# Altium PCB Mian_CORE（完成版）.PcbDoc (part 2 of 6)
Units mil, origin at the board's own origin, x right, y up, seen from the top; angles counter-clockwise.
Board outline 2755.91 x 1771.65 mil, 4 copper layers (TOP, GND02, PWR03, BOTTOM); 61 components, 130 nets, 4907 pads, 497 vias.
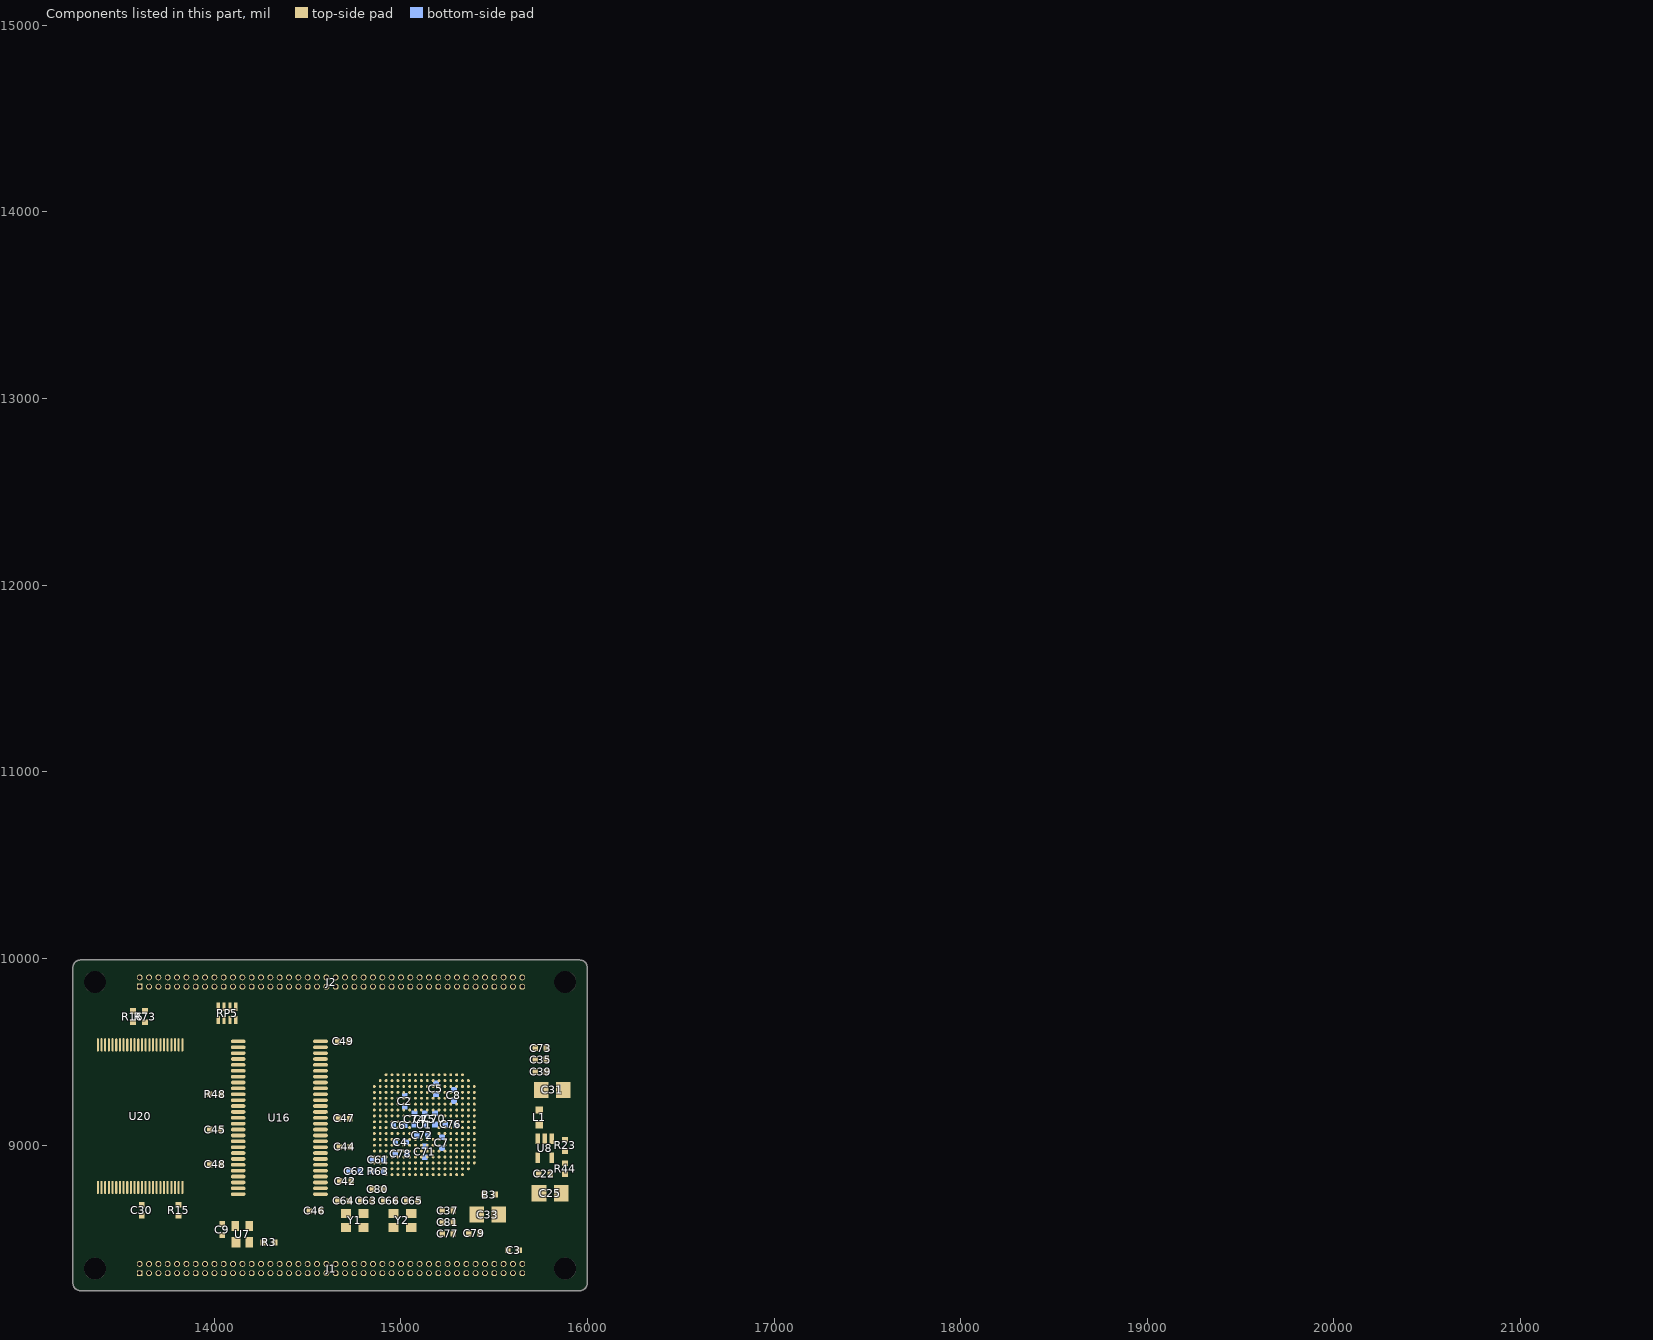
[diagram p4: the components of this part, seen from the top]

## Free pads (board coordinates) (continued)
  round 6 on Drill Drawing: 1(17801.05,10105.03) 1(17801.05,10325.03) 1(17801.05,10545.03) 1(17804.4,9445.61) 1(17804.4,9445.61) 1(17804.4,9480.61) 1(17824.4,9445.61) 1(17831.9,9445.61) 1(17836.4,9457.86) 1(17844.4,9480.61) 1(17844.4,9480.61) 1(17852.4,9457.86) 1(17856.9,9445.61) 1(17864.4,9480.61) 1(17874.4,9445.61) 1(17874.4,9461.36) 1(17874.4,9461.36) 1(17874.4,9461.36) 1(17881.05,10085.03) 1(17881.05,10085.03) 1(17881.05,10125.03) 1(17881.05,10125.03) 1(17881.05,10305.03) 1(17881.05,10305.03) 1(17881.05,10345.03) 1(17881.05,10345.03) 1(17881.05,10525.03) 1(17881.05,10525.03) 1(17881.05,10565.03) 1(17881.05,10565.03) 1(17884.4,9480.61) 1(17889.05,8796.36) 1(17889.05,8796.36) 1(17889.05,8831.36) 1(17894.4,9445.61) 1(17894.4,9445.61) 1(17894.4,9463.69) 1(17894.4,9480.61) 1(17894.4,9480.61) 1(17906.4,9463.69) 1(17909.05,8796.36) 1(17914.4,9445.61) 1(17914.4,9480.61) 1(17916.55,8796.36) 1(17921.05,8808.61) 1(17924.4,9445.61) 1(17924.4,9462.53) 1(17924.4,9480.61) 1(17924.4,9480.61) 1(17929.05,8831.36) 1(17929.05,8831.36) 1(17936.05,10105.03) 1(17936.05,10105.03) 1(17936.05,10105.03) 1(17936.05,10325.03) 1(17936.05,10325.03) 1(17936.05,10325.03) 1(17936.05,10545.03) 1(17936.05,10545.03) 1(17936.05,10545.03) 1(17936.9,9462.53) 1(17936.9,9462.53) 1(17936.9,9462.53) 1(17936.9,9480.61) 1(17936.9,9480.61) 1(17937.05,8808.61) 1(17940.4,9464.28) 1(17940.4,9464.28) 1(17940.9,9478.86) 1(17940.9,9478.86) 1(17941.55,8796.36) 1(17943.4,9467.19) 1(17943.4,9467.19) 1(17943.4,9476.53) 1(17943.4,9476.53) 1(17944.4,9445.61) 1(17944.4,9471.86) 1(17944.4,9471.86) 1(17949.05,8831.36) 1(17959.05,8796.36) 1(17959.05,8812.11) 1(17959.05,8812.11) 1(17959.05,8812.11) 1(17969.05,8831.36) 1(17979.05,8796.36) 1(17979.05,8796.36) 1(17979.05,8814.44) 1(17979.05,8831.36) 1(17979.05,8831.36) 1(17991.05,8814.44) 1(17999.05,8796.36) 1(17999.05,8831.36) 1(18009.05,8796.36) 1(18009.05,8813.28) 1(18009.05,8831.36) 1(18009.05,8831.36) 1(18021.55,8813.28) 1(18021.55,8813.28) 1(18021.55,8813.28) 1(18021.55,8831.36) 1(18021.55,8831.36) 1(18025.05,8815.03) 1(18025.05,8815.03) 1(18025.55,8829.61) 1(18025.55,8829.61) 1(18028.05,8817.94) 1(18028.05,8817.94) 1(18028.05,8827.28) 1(18028.05,8827.28) 1(18029.05,8796.36) 1(18029.05,8822.61) 1(18029.05,8822.61) 1(18031.55,10069.6) 1(18031.55,10119.6) 1(18031.55,10289.29) 1(18031.55,10339.29) 1(18031.55,10508.97) 1(18031.55,10558.97) 1(18066.55,10054.6) 1(18066.55,10274.29) 1(18066.55,10493.97) 1(18071.55,10159.6) 1(18071.55,10379.29) 1(18071.55,10598.97) 1(18116.55,10054.6) 1(18116.55,10274.29) 1(18116.55,10493.97) 1(18121.55,10159.6) 1(18121.55,10379.29) 1(18121.55,10598.97) 1(18166.55,10054.6) 1(18166.55,10274.29) 1(18166.55,10493.97) 1(18171.55,10159.6) 1(18171.55,10379.29) 1(18171.55,10598.97) 1(18221.55,10159.6) 1(18221.55,10379.29) 1(18221.55,10598.97) 1(18271.55,10159.6) 1(18271.55,10379.29) 1(18271.55,10598.97) 1(18278.95,9479.58) 1(18285.95,9444.58) 1(18285.95,9444.58) 1(18293.95,9479.58) 1(18293.95,9479.58) 1(18301.95,9444.58) 1(18301.95,9444.58) 1(18308.95,9479.58) 1(18313.58,8840.03) 1(18317.95,9444.58) 1(18317.95,9479.58) 1(18320.58,8805.03) 1(18320.58,8805.03) 1(18323.95,9444.58) 1(18323.95,9479.58) 1(18328.58,8840.03) 1(18328.58,8840.03) 1(18329.95,9444.58) 1(18329.95,9479.58) 1(18336.58,8805.03) 1(18336.58,8805.03) 1(18342.95,9444.58) 1(18342.95,9444.58) 1(18342.95,9479.58) 1(18342.95,9479.58) 1(18343.58,8840.03) 1(18352.58,8805.03) 1(18352.58,8840.03) 1(18352.95,9444.58) 1(18352.95,9444.58) 1(18352.95,9479.58) 1(18352.95,9479.58) 1(18356.95,9446.33) 1(18356.95,9446.33) 1(18356.95,9477.83) 1(18356.95,9477.83) 1(18358.58,8805.03) 1(18358.58,8840.03) 1(18359.95,9448.66) 1(18359.95,9448.66) 1(18359.95,9475.5) 1(18359.95,9475.5) 1(18362.45,9452.16) 1(18362.45,9452.16) 1(18362.45,9472) 1(18362.45,9472) 1(18364.45,9456.25) 1(18364.45,9456.25) 1(18364.45,9467.91) 1(18364.45,9467.91) 1(18364.58,8805.03) 1(18364.58,8840.03) 1(18364.95,9462.08) 1(18364.95,9462.08) 1(18372.45,9479.58) 1(18377.58,8805.03) 1(18377.58,8805.03) 1(18377.58,8840.03) 1(18377.58,8840.03) 1(18383.95,9444.58) 1(18383.95,9479.58) 1(18387.58,8805.03) 1(18387.58,8805.03) 1(18387.58,8840.03) 1(18387.58,8840.03) 1(18391.58,8806.78) 1(18391.58,8806.78) 1(18391.58,8838.28) 1(18391.58,8838.28) 1(18394.58,8809.11) 1(18394.58,8809.11) 1(18394.58,8835.95) 1(18394.58,8835.95) 1(18395.45,9479.58) 1(18397.08,8812.61) 1(18397.08,8812.61) 1(18397.08,8832.45) 1(18397.08,8832.45) 1(18399.08,8816.7) 1(18399.08,8816.7) 1(18399.08,8828.36) 1(18399.08,8828.36) 1(18399.58,8822.53) 1(18399.58,8822.53) 1(18403.45,9444.58) 1(18403.45,9462.08) 1(18403.45,9479.58) 1(18407.08,8840.03) 1(18418.58,8805.03) 1(18418.58,8840.03) 1(18424.45,9444.58) 1(18424.45,9462.08) 1(18424.45,9479.58) 1(18430.08,8840.03) 1(18438.08,8805.03) 1(18438.08,8822.53) 1(18438.08,8840.03) 1(18459.08,8805.03) 1(18459.08,8822.53) 1(18459.08,8840.03) 1(18511.26,9452.75) 1(18511.26,9452.75) 1(18511.26,9476.08) 1(18511.26,9476.08) 1(18513.76,9446.92) 1(18513.76,9446.92) 1(18513.76,9481.92) 1(18513.76,9481.92) 1(18518.58,8805.03) 1(18518.58,8805.03) 1(18518.58,8828.36) 1(18518.58,8828.36) 1(18518.76,9441.08) 1(18518.76,9487.75) 1(18521.08,8799.2) 1(18521.08,8799.2) 1(18521.08,8834.2) 1(18521.08,8834.2) 1(18526.08,8793.36) 1(18526.08,8840.03) 1(18536.26,9452.75) 1(18536.26,9469.67) 1(18536.26,9476.08) 1(18537.76,9472.58) 1(18537.76,9472.58) 1(18540.26,9474.92) 1(18540.26,9474.92) 1(18543.58,8805.03) 1(18543.58,8821.95) 1(18543.58,8828.36) 1(18543.76,9476.08) 1(18543.76,9476.08) 1(18545.08,8824.86) 1(18545.08,8824.86) 1(18547.26,9474.92) 1(18547.26,9474.92) 1(18547.58,8827.2) 1(18547.58,8827.2) 1(18549.76,9472.58) 1(18549.76,9472.58) 1(18551.08,8828.36) 1(18551.08,8828.36) 1(18551.26,9452.75) 1(18551.26,9469.67) 1(18551.26,9469.67) 1(18551.26,9469.67) 1(18552.76,9472.58) 1(18552.76,9472.58) 1(18554.58,8827.2) 1(18554.58,8827.2) 1(18555.26,9474.92) 1(18555.26,9474.92) 1(18557.08,8824.86) 1(18557.08,8824.86) 1(18558.58,8805.03) 1(18558.58,8821.95) 1(18558.58,8821.95) 1(18558.58,8821.95) 1(18558.76,9476.08) 1(18558.76,9476.08) 1(18560.08,8824.86) 1(18560.08,8824.86) 1(18562.26,9474.92) 1(18562.26,9474.92) 1(18562.58,8827.2) 1(18562.58,8827.2) 1(18564.76,9472.58) 1(18564.76,9472.58) 1(18566.08,8828.36) 1(18566.08,8828.36) 1(18566.26,9452.75) 1(18566.26,9469.08) 1(18566.26,9469.08) 1(18569.58,8827.2) 1(18569.58,8827.2) 1(18572.08,8824.86) 1(18572.08,8824.86) 1(18573.58,8805.03) 1(18573.58,8821.36) 1(18573.58,8821.36) 1(18580.26,9486) 1(18580.26,9486) 1(18580.26,9487.17) 1(18580.26,9487.17) 1(18581.26,9452.75) 1(18581.26,9476.08) 1(18581.26,9485.42) 1(18581.26,9485.42) 1(18581.26,9487.75) 1(18581.26,9487.75) 1(18582.26,9486) 1(18582.26,9486) 1(18582.26,9487.17) 1(18582.26,9487.17) 1(18587.58,8838.28) 1(18587.58,8838.28) 1(18587.58,8839.45) 1(18587.58,8839.45) 1(18588.58,8805.03) 1(18588.58,8828.36) 1(18588.58,8837.7) 1(18588.58,8837.7) 1(18588.58,8840.03) 1(18588.58,8840.03) 1(18589.58,8838.28) 1(18589.58,8838.28) 1(18589.58,8839.45) 1(18589.58,8839.45) 1(18611.26,9452.75) 1(18611.26,9487.75) 1(18614.09,11174.91) 1(18614.09,11174.91) 1(18614.09,11237.91) 1(18618.26,11157.91) 1(18618.58,8805.03) 1(18618.58,8840.03) 1(18643.76,9441.08) 1(18643.76,9487.75) 1(18645.43,11174.91) 1(18648.76,9446.92) 1(18648.76,9446.92) 1(18648.76,9481.92) 1(18648.76,9481.92) 1(18651.08,8793.36) 1(18651.08,8840.03) 1(18651.26,9452.75) 1(18651.26,9452.75) 1(18651.26,9476.08) 1(18651.26,9476.08) 1(18656.08,8799.2) 1(18656.08,8799.2) 1(18656.08,8834.2) 1(18656.08,8834.2) 1(18658.58,8805.03) 1(18658.58,8805.03) 1(18658.58,8828.36) 1(18658.58,8828.36) 1(18673.18,11174.91) 1(18680.23,11196.96) 1(18692.76,11237.91) 1(18692.76,11237.91) 1(18705.29,11196.96) 1(18712.34,11174.91) 1(18727.35,9837.19) 1(18727.35,9837.19) 1(18727.35,9870.79) 1(18727.35,9900.19) 1(18727.35,9900.19) 1(18735.81,11079.31) 1(18738.94,11118.16) 1(18738.94,11118.16) 1(18740.09,11237.91) 1(18740.51,11125.51) 1(18740.51,11125.51) 1(18741.29,11110.81) 1(18741.29,11110.81) 1(18742.08,11074.06) 1(18742.08,11074.06) 1(18744.43,11130.76) 1(18744.43,11130.76) 1(18746.78,11106.61) 1(18746.78,11106.61) 1(18748.5,9900.19) 1(18748.5,9900.19) 1(18749.13,11070.91) 1(18749.13,11070.91) 1(18749.91,11133.91) 1(18749.91,11133.91) 1(18751.64,9870.79) 1(18751.64,9870.79) 1(18751.64,9870.79) 1(18753.2,9837.19) 1(18753.2,9837.19) 1(18753.99,9897.04) 1(18753.99,9897.04) 1(18754.77,9873.94) 1(18754.77,9873.94) 1(18755.39,11070.91) 1(18755.39,11070.91) 1(18755.39,11133.91) 1(18755.39,11133.91) 1(18755.76,11174.91) 1(18755.76,11203.26) 1(18755.76,11203.26) 1(18755.76,11203.26) 1(18756.18,11104.51) 1(18756.18,11104.51) 1(18757.12,9868.69) 1(18757.12,9868.69) 1(18757.12,9879.19) 1(18757.12,9879.19) 1(18757.12,9892.84) 1(18757.12,9892.84) 1(18758.69,9841.39) 1(18758.69,9841.39) 1(18758.69,9886.54) 1(18758.69,9886.54) 1(18760.88,11131.81) 1(18760.88,11131.81) 1(18761.66,11074.06) 1(18761.66,11074.06) 1(18761.82,9847.69) 1(18761.82,9847.69) 1(18761.82,9862.39) 1(18761.82,9862.39) 1(18763.23,11100.31) 1(18763.23,11100.31) 1(18763.39,9855.04) 1(18763.39,9855.04) 1(18765.1,10833.91) 1(18765.58,11126.56) 1(18766.36,11079.31) 1(18766.36,11079.31) 1(18767.14,11094.01) 1(18767.14,11094.01) 1(18768.71,11086.66) 1(18768.71,11086.66) 1(18771.43,11237.91) 1(18783.12,10770.91) 1(18783.12,10833.91) 1(18787.22,9864.49) 1(18787.22,9864.49) 1(18787.22,9872.89) 1(18787.22,9872.89) 1(18788.79,9856.09) 1(18788.79,9856.09) 1(18788.79,9881.29) 1(18788.79,9881.29) 1(18791.92,9848.74) 1(18791.92,9848.74) 1(18791.92,9888.64) 1(18791.92,9888.64) 1(18795.68,11099.26) 1(18795.68,11099.26) 1(18796.46,11108.71) 1(18796.46,11108.71) 1(18796.62,9842.44) 1(18796.62,9842.44) 1(18796.62,9894.94) 1(18796.62,9894.94) 1(18797.24,11089.81) 1(18797.24,11089.81) 1(18799.59,11083.51) 1(18799.59,11083.51) 1(18799.59,11119.21) 1(18799.59,11119.21) 1(18801.14,10833.91) 1(18802.1,9838.24) 1(18802.1,9838.24) 1(18802.1,9899.14) 1(18802.1,9899.14) 1(18803.09,11174.91) 1(18803.09,11174.91) 1(18803.09,11207.46) 1(18803.09,11237.91) 1(18803.09,11237.91) 1(18803.51,11125.51) 1(18803.51,11125.51) 1(18804.29,11077.21) 1(18804.29,11077.21) 1(18808.37,9837.19) 1(18808.37,9837.19) 1(18808.37,9900.19) 1(18808.37,9900.19) 1(18808.99,11130.76) 1(18808.99,11130.76) 1(18809.78,11073.01) 1(18809.78,11073.01) 1(18814.64,9838.24) 1(18814.64,9838.24) 1(18814.64,9899.14) 1(18814.64,9899.14) 1(18815.26,11070.91) 1(18815.26,11070.91) 1(18816.04,11133.91) 1(18816.04,11133.91) 1(18820.12,9842.44) 1(18820.12,9842.44) 1(18820.12,9894.94) 1(18820.12,9894.94) 1(18820.74,11070.91) 1(18820.74,11070.91) 1(18821.89,11207.46) 1(18822.31,11133.91) 1(18822.31,11133.91) 1(18824.82,9848.74) 1(18824.82,9848.74) 1(18824.82,9888.64) 1(18824.82,9888.64) 1(18824.97,10798.21) 1(18824.97,10798.21) 1(18824.97,10806.61) 1(18824.97,10806.61) 1(18826.23,11073.01) 1(18826.23,11073.01) 1(18826.54,10789.81) 1(18826.54,10789.81) 1(18826.54,10815.01) 1(18826.54,10815.01) 1(18827.79,11131.81) 1(18827.79,11131.81) 1(18827.95,9856.09) 1(18827.95,9856.09) 1(18827.95,9881.29) 1(18827.95,9881.29) 1(18829.52,9864.49) 1(18829.52,9864.49) 1(18829.52,9872.89) 1(18829.52,9872.89) 1(18829.67,10782.46) 1(18829.67,10782.46) 1(18829.67,10822.36) 1(18829.67,10822.36) 1(18830.93,11076.16) 1(18830.93,11076.16) 1(18832.49,11128.66) 1(18834.37,10776.16) 1(18834.37,10776.16) 1(18834.37,10828.66) 1(18834.37,10828.66) 1(18834.43,11174.91) 1(18834.43,11237.91) 1(18834.84,11080.36) 1(18839.85,10771.96) 1(18839.85,10771.96) 1(18839.85,10832.86) 1(18839.85,10832.86) 1(18846.12,10770.91) 1(18846.12,10770.91) 1(18846.12,10833.91) 1(18846.12,10833.91) 1(18852.39,10771.96) 1(18852.39,10771.96) 1(18852.39,10832.86) 1(18852.39,10832.86) 1(18853.35,9900.19) 1(18856.69,9449.95) 1(18856.69,9484.95) 1(18857.87,10776.16) 1(18857.87,10776.16) 1(18857.87,10828.66) 1(18857.87,10828.66) 1(18858.68,11070.91) 1(18862.57,10782.46) 1(18862.57,10782.46) 1(18862.57,10822.36) 1(18862.57,10822.36) 1(18862.69,9449.95) 1(18862.69,9484.95) 1(18865.7,10789.81) 1(18865.7,10789.81) 1(18865.7,10815.01) 1(18865.7,10815.01) 1(18865.73,11092.96) 1(18866.09,11174.91) 1(18866.09,11205.36) 1(18866.09,11237.91) 1(18866.09,11237.91) 1(18867.27,10798.21) 1(18867.27,10798.21) 1(18867.27,10806.61) 1(18867.27,10806.61) 1(18868.69,9449.95) 1(18868.69,9484.95) 1(18871.37,9837.19) 1(18871.37,9900.19) 1(18878.26,11133.91) 1(18878.26,11133.91) 1(18879.69,9449.95) 1(18879.69,9484.95) 1(18879.69,9484.95) 1(18885.68,11205.36) 1(18885.68,11205.36) 1(18885.68,11205.36) 1(18885.68,11237.91) 1(18885.68,11237.91) 1(18889.39,9900.19) 1(18890.79,11092.96) 1(18891.16,11208.51) 1(18891.16,11208.51) 1(18891.94,11234.76) 1(18891.94,11234.76) 1(18892.69,9455.78) 1(18892.69,9455.78) 1(18893.45,10770.91) 1(18893.45,10797.16) 1(18893.45,10833.91) 1(18893.45,10833.91) 1(18895.86,11213.76) 1(18895.86,11213.76) 1(18895.86,11230.56) 1(18895.86,11230.56) 1(18897.43,11174.91) 1(18897.43,11222.16) 1(18897.43,11222.16) 1(18897.84,11070.91) 1(18905.69,9449.95) 1(18905.69,9484.95) 1(18905.69,9484.95) 1(18906.83,8795.97) 1(18906.83,8830.97) 1(18912.25,10797.16) 1(18912.25,10797.16) 1(18912.25,10833.91) 1(18912.25,10833.91) 1(18912.69,9449.95) 1(18912.69,9464.53) 1(18912.69,9484.95) 1(18912.69,9484.95) 1(18912.83,8795.97) 1(18912.83,8830.97) 1(18916.35,9900.19) 1(18918.52,10830.76) 1(18918.52,10830.76) 1(18918.83,8795.97) 1(18918.83,8830.97) 1(18919.3,10800.31) 1(18919.3,10800.31) 1(18923.22,10806.61) 1(18923.22,10806.61) 1(18923.22,10823.41) 1(18923.22,10823.41) 1(18924.69,9464.53) 1(18924.69,9464.53) 1(18924.69,9484.95) 1(18924.69,9484.95) 1(18924.79,10815.01) 1(18924.79,10815.01) 1(18925.59,11070.91) 1(18925.59,11070.91) 1(18925.59,11133.91) 1(18928.69,9483.2) 1(18928.69,9483.2) 1(18929.19,9466.28) 1(18929.19,9466.28) 1(18929.83,8795.97) 1(18929.83,8830.97) 1(18929.83,8830.97) 1(18931.69,9469.78) 1(18931.69,9469.78) 1(18931.69,9479.12) 1(18931.69,9479.12) 1(18932.69,9474.45) 1(18932.69,9474.45) 1(18934.37,9837.19) 1(18934.37,9900.19) 1(18942.69,9449.95) 1(18942.69,9449.95) 1(18942.69,9468.03) 1(18942.69,9484.95) 1(18942.69,9484.95) 1(18942.83,8801.8) 1(18942.83,8801.8) 1(18952.39,9900.19) 1(18954.69,9468.03) 1(18955.83,8795.97) 1(18955.83,8830.97) 1(18955.83,8830.97) 1(18956.93,11070.91) 1(18962.69,9449.95) 1(18962.69,9484.95) 1(18962.83,8795.97) 1(18962.83,8810.55) 1(18962.83,8830.97) 1(18962.83,8830.97) 1(18971.69,9449.95) 1(18971.69,9449.95) 1(18971.69,9484.95) 1(18971.69,9484.95) 1(18974.83,8810.55) 1(18974.83,8810.55) 1(18974.83,8830.97) 1(18974.83,8830.97) 1(18976.22,9864.49) 1(18976.22,9864.49) 1(18976.22,9872.89) 1(18976.22,9872.89) 1(18977.79,9856.09) 1(18977.79,9856.09) 1(18977.79,9881.29) 1(18977.79,9881.29) 1(18978.83,8829.22) 1(18978.83,8829.22) 1(18979.33,8812.3) 1(18979.33,8812.3) 1(18980.92,9848.74) 1(18980.92,9848.74) 1(18980.92,9888.64) 1(18980.92,9888.64) 1(18981.69,9449.95) 1(18981.69,9449.95) 1(18981.69,9484.95) 1(18981.69,9484.95) 1(18981.83,8815.8) 1(18981.83,8815.8) 1(18981.83,8825.14) 1(18981.83,8825.14) 1(18982.83,8820.47) 1(18982.83,8820.47) 1(18985.62,9842.44) 1(18985.62,9842.44) 1(18985.62,9894.94) 1(18985.62,9894.94) 1(18985.69,9451.7) 1(18985.69,9451.7) 1(18985.69,9483.2) 1(18985.69,9483.2) 1(18988.59,11070.91) 1(18988.59,11070.91) 1(18988.59,11103.46) 1(18988.59,11133.91) 1(18988.59,11133.91) 1(18988.69,9454.03) 1(18988.69,9454.03) 1(18988.69,9480.87) 1(18988.69,9480.87) 1(18991.1,9838.24) 1(18991.1,9838.24) 1(18991.1,9899.14) 1(18991.1,9899.14) 1(18991.19,9457.53) 1(18991.19,9457.53) 1(18991.19,9477.37) 1(18991.19,9477.37) 1(18991.31,11183.31) 1(18992.83,8795.97) 1(18992.83,8795.97) 1(18992.83,8814.05) 1(18992.83,8830.97) 1(18992.83,8830.97) 1(18993.19,9461.62) 1(18993.19,9461.62) 1(18993.19,9473.28) 1(18993.19,9473.28) 1(18993.69,9467.45) 1(18993.69,9467.45) 1(18994.44,11222.16) 1(18994.44,11222.16) 1(18996.01,11229.51) 1(18996.01,11229.51) 1(18996.79,11214.81) 1(18996.79,11214.81) 1(18997.37,9837.19) 1(18997.37,9837.19) 1(18997.37,9900.19) 1(18997.37,9900.19) 1(18997.58,11178.06) 1(18997.58,11178.06) 1(18999.93,11234.76) 1(18999.93,11234.76) 1(19000.19,9449.95) 1(19002.28,11210.61) 1(19002.28,11210.61) 1(19003.64,9838.24) 1(19003.64,9838.24) 1(19003.64,9899.14) 1(19003.64,9899.14) 1(19004.63,11174.91) 1(19004.63,11174.91) 1(19004.69,9462.2) 1(19004.83,8814.05) 1(19005.41,11237.91) 1(19005.41,11237.91) 1(19007.39,11103.46) 1(19009.12,9842.44) 1(19009.12,9842.44) 1(19009.12,9894.94) 1(19009.12,9894.94) 1(19010.89,11174.91) 1(19010.89,11174.91) 1(19010.89,11237.91) 1(19010.89,11237.91) 1(19011.68,11208.51) 1(19011.68,11208.51) 1(19012.69,9484.95) 1(19012.69,9484.95) 1(19012.83,8795.97) 1(19012.83,8830.97) 1(19013.82,9848.74) 1(19013.82,9848.74) 1(19013.82,9888.64) 1(19013.82,9888.64) 1(19016.38,11235.81) 1(19016.38,11235.81) 1(19016.95,9856.09) 1(19016.95,9856.09) 1(19016.95,9881.29) 1(19016.95,9881.29) 1(19017.16,11178.06) 1(19017.16,11178.06) 1(19018.52,9864.49) 1(19018.52,9864.49) 1(19018.52,9872.89) 1(19018.52,9872.89) 1(19018.67,10779.31) 1(19018.73,11204.31) 1(19018.73,11204.31) 1(19019.93,11070.91) 1(19019.93,11133.91) 1(19020.69,9462.2) 1(19021.08,11230.56) 1(19021.8,10818.16) 1(19021.8,10818.16) 1(19021.83,8795.97) 1(19021.83,8795.97) 1(19021.83,8830.97) 1(19021.83,8830.97) 1(19021.86,11183.31) 1(19021.86,11183.31) 1(19022.64,11198.01) 1(19022.64,11198.01) 1(19023.37,10825.51) 1(19023.37,10825.51) 1(19024.15,10810.81) 1(19024.15,10810.81) 1(19024.21,11190.66) 1(19024.21,11190.66) 1(19024.94,10774.06) 1(19024.94,10774.06) 1(19025.19,9449.95) 1(19027.29,10830.76) 1(19027.29,10830.76) 1(19029.64,10806.61) 1(19029.64,10806.61) 1(19031.19,9449.95) 1(19031.19,9484.95) 1(19031.19,9484.95) 1(19031.83,8795.97) 1(19031.83,8795.97) 1(19031.83,8830.97) 1(19031.83,8830.97) 1(19031.99,10770.91) 1(19031.99,10770.91) 1(19032.77,10833.91) 1(19032.77,10833.91) 1(19035.83,8797.72) 1(19035.83,8797.72) 1(19035.83,8829.22) 1(19035.83,8829.22) 1(19038.25,10770.91) 1(19038.25,10770.91) 1(19038.25,10833.91) 1(19038.25,10833.91) 1(19038.83,8800.05) 1(19038.83,8800.05) 1(19038.83,8826.89) 1(19038.83,8826.89) 1(19039.04,10804.51) 1(19039.04,10804.51) 1(19040,9837.19) 1(19040,9900.19) 1(19040,9900.19) 1(19041.33,8803.55) 1(19041.33,8803.55) 1(19041.33,8823.39) 1(19041.33,8823.39) 1(19043.33,8807.64) 1(19043.33,8807.64) 1(19043.33,8819.3) 1(19043.33,8819.3) 1(19043.74,10831.81) 1(19043.74,10831.81) 1(19043.83,8813.47) 1(19043.83,8813.47) 1(19044.52,10774.06) 1(19044.52,10774.06) 1(19046.09,10800.31) 1(19046.09,10800.31) 1(19048.44,10826.56) 1(19049.22,10779.31) 1(19049.22,10779.31) 1(19050,10794.01) 1(19050,10794.01) 1(19050.33,8795.97) 1(19051.57,10786.66) 1(19051.57,10786.66) 1(19052.74,11237.91) 1(19054.19,9449.95) 1(19054.19,9449.95) 1(19054.19,9484.95) 1(19054.83,8808.22) 1(19060.19,9465.7) 1(19060.19,9465.7) 1(19060.37,9847.69) 1(19060.37,9847.69) 1(19060.69,9470.95) 1(19060.69,9470.95) 1(19061.19,9460.45) 1(19061.19,9460.45) 1(19062.69,9456.95) 1(19062.69,9456.95) 1(19062.69,9476.78) 1(19062.69,9476.78) 1(19062.83,8830.97) 1(19062.83,8830.97) 1(19065.19,9480.28) 1(19065.19,9480.28) 1(19065.69,11069.86) 1(19065.69,11069.86) 1(19065.69,11071.96) 1(19065.69,11071.96) 1(19065.69,11098.21) 1(19065.69,11098.21) 1(19065.69,11100.31) 1(19065.69,11100.31) 1(19065.69,9453.45) 1(19065.69,9453.45) 1(19067.26,11068.81) 1(19067.26,11068.81) 1(19067.26,11073.01) 1(19067.26,11073.01) 1(19067.26,11097.16) 1(19067.26,11097.16) 1(19067.26,11101.36) 1(19067.26,11101.36) 1(19068.69,9483.2) 1(19068.69,9483.2) 1(19068.83,11069.86) 1(19068.83,11069.86) 1(19068.83,11071.96) 1(19068.83,11071.96) 1(19068.83,11098.21) 1(19068.83,11098.21) 1(19068.83,11100.31) 1(19068.83,11100.31) 1(19069.19,9451.12) 1(19069.19,9451.12) 1(19070.76,11174.91) 1(19070.76,11237.91) 1(19070.83,8808.22) 1(19072.69,9449.95) 1(19072.69,9449.95) 1(19073.19,9484.95) 1(19073.19,9484.95) 1(19075.33,8795.97) 1(19076.19,9449.95) 1(19076.19,9449.95) 1(19077.19,9484.95) 1(19077.19,9484.95) 1(19079.69,9451.12) 1(19079.69,9451.12) 1(19080.69,9483.78) 1(19080.69,9483.78) 1(19080.74,9837.19) 1(19080.74,9900.19) 1(19080.74,9900.19) 1(19081.33,8795.97) 1(19081.33,8830.97) 1(19081.33,8830.97) 1(19082.69,9452.87) 1(19082.69,9452.87) 1(19083.69,9482.03) 1(19085.19,9455.2) 1(19088.72,10770.91) 1(19088.72,10833.91) 1(19088.78,11237.91) 1(19092.69,9449.95) 1(19092.69,9449.95) 1(19092.69,9468.03) 1(19092.69,9484.95) 1(19092.69,9484.95) 1(19098.12,10770.91) 1(19098.12,10833.91) 1(19104.33,8795.97) 1(19104.33,8795.97) 1(19104.33,8830.97) 1(19104.69,9468.03) 1(19107.52,10770.91) 1(19107.52,10833.91) 1(19110.33,8811.72) 1(19110.33,8811.72) 1(19110.83,8816.97) 1(19110.83,8816.97) 1(19111.33,8806.47) 1(19111.33,8806.47) 1(19112.24,11070.91) 1(19112.24,11133.91) 1(19112.24,11133.91) 1(19112.69,9449.95) 1(19112.69,9484.95) 1(19112.83,8802.97) 1(19112.83,8802.97) 1(19112.83,8822.8) 1(19112.83,8822.8) 1(19114.18,11174.91) 1(19115.33,8826.3) 1(19115.33,8826.3) 1(19115.83,8799.47) 1(19115.83,8799.47) 1(19118.83,8829.22) 1(19118.83,8829.22) 1(19119.33,8797.14) 1(19119.33,8797.14) 1(19121.23,11196.96) 1(19122.83,8795.97) 1(19122.83,8795.97) 1(19123.33,8830.97) 1(19123.33,8830.97) 1(19126.33,8795.97) 1(19126.33,8795.97) 1(19127.33,8830.97) 1(19127.33,8830.97) 1(19129.83,8797.14) 1(19129.83,8797.14) 1(19130.83,8829.8) 1(19130.83,8829.8) 1(19132.83,8798.89) 1(19132.83,8798.89) 1(19133.76,11237.91) 1(19133.76,11237.91) 1(19133.83,8828.05) 1(19135.33,8801.22) 1(19142.83,8795.97) 1(19142.83,8795.97) 1(19142.83,8814.05) 1(19142.83,8830.97) 1(19142.83,8830.97) 1(19143.89,10770.91) 1(19143.89,10770.91) 1(19143.89,10833.91) 1(19143.89,10833.91) 1(19146.29,11196.96) 1(19148.28,11070.91) 1(19148.28,11070.91) 1(19148.28,11133.91) 1(19153.34,11174.91) 1(19154.83,8814.05) 1(19159.55,10770.91) 1(19159.55,10770.91) 1(19159.55,10833.91) 1(19159.55,10833.91) 1(19162.83,8795.97) 1(19162.83,8830.97) 1(19165.82,10774.06) 1(19165.82,10774.06) 1(19165.82,10830.76) 1(19165.82,10830.76) 1(19169.92,9845.59) 1(19170.52,10778.26) 1(19170.52,10778.26) 1(19170.52,10826.56) 1(19170.52,10826.56) 1(19172.11,11098.21) 1(19172.11,11098.21) 1(19172.11,11106.61) 1(19172.11,11106.61) 1(19173.05,9884.44) 1(19173.05,9884.44) 1(19173.68,11089.81) 1(19173.68,11089.81) 1(19173.68,11115.01) 1(19173.68,11115.01) 1(19174.44,10784.56) 1(19174.44,10784.56) 1(19174.44,10820.26) 1(19174.44,10820.26) 1(19174.62,9891.79) 1(19174.62,9891.79) 1(19175.4,9877.09) 1(19175.4,9877.09) 1(19176.19,9840.34) 1(19176.19,9840.34) 1(19176.81,11082.46) 1(19176.81,11082.46) 1(19176.81,11122.36) 1(19176.81,11122.36) 1(19177.18,11203.26) 1(19177.18,11203.26) 1(19177.57,10791.91) 1(19177.57,10791.91) 1(19177.57,10812.91) 1(19177.57,10812.91) 1(19177.96,11212.71) 1(19177.96,11212.71) 1(19178.35,10802.41) 1(19178.35,10802.41) 1(19178.54,9897.04) 1(19178.54,9897.04) 1(19178.74,11193.81) 1(19178.74,11193.81) 1(19180.89,9872.89) 1(19180.89,9872.89) 1(19181.09,11187.51) 1(19181.09,11187.51) 1(19181.09,11223.21) 1(19181.09,11223.21) 1(19181.51,11076.16) 1(19181.51,11076.16) 1(19181.51,11128.66) 1(19181.51,11128.66) 1(19183.24,9837.19) 1(19183.24,9837.19) 1(19184.02,9900.19) 1(19184.02,9900.19) 1(19185.01,11229.51) 1(19185.01,11229.51) 1(19185.79,11181.21) 1(19185.79,11181.21) 1(19186.99,11071.96) 1(19186.99,11071.96) 1(19186.99,11132.86) 1(19186.99,11132.86) 1(19189.5,9837.19) 1(19189.5,9837.19) 1(19189.5,9900.19) 1(19189.5,9900.19) 1(19190.29,9870.79) 1(19190.29,9870.79) 1(19190.49,11234.76) 1(19190.49,11234.76) 1(19191.28,11177.01) 1(19191.28,11177.01) 1(19193.26,11070.91) 1(19193.26,11070.91) 1(19193.26,11133.91) 1(19193.26,11133.91) 1(19194.99,9898.09) 1(19194.99,9898.09) 1(19195.77,9840.34) 1(19195.77,9840.34) 1(19196.76,11174.91) 1(19196.76,11174.91) 1(19197.34,9866.59) 1(19197.34,9866.59) 1(19197.54,11237.91) 1(19197.54,11237.91) 1(19199.53,11071.96) 1(19199.53,11071.96) 1(19199.53,11132.86) 1(19199.53,11132.86) 1(19199.69,9892.84) 1(19200.47,9845.59) 1(19200.47,9845.59) 1(19201.25,9860.29) 1(19201.25,9860.29) 1(19202.24,11174.91) 1(19202.24,11174.91) 1(19202.82,9852.94) 1(19202.82,9852.94) 1(19203.81,11237.91) 1(19203.81,11237.91) 1(19205.01,11076.16) 1(19205.01,11076.16) 1(19205.01,11128.66) 1(19205.01,11128.66) 1(19207.73,11177.01) 1(19207.73,11177.01) 1(19208.45,10770.91) 1(19208.45,10770.91) 1(19208.45,10803.46) 1(19208.45,10833.91) 1(19208.45,10833.91) 1(19209.29,11235.81) 1(19209.29,11235.81) 1(19209.71,11082.46) 1(19209.71,11082.46) 1(19209.71,11122.36) 1(19209.71,11122.36) 1(19212.43,11180.16) 1(19212.43,11180.16) 1(19212.84,11089.81) 1(19212.84,11089.81) 1(19212.84,11115.01) 1(19212.84,11115.01) 1(19213.99,11232.66) 1(19214.41,11098.21) 1(19214.41,11098.21) 1(19214.41,11106.61) 1(19214.41,11106.61) 1(19216.34,11184.36) 1(19227.25,10803.46) 1(19238.24,11070.91) 1(19238.24,11133.91) 1(19238.24,11133.91) 1(19239.79,10770.91) 1(19239.79,10833.91) 1(19239.97,9837.19) 1(19239.97,9900.19) 1(19240,9453.12) 1(19240,9453.12) 1(19240,9476.45) 1(19240,9476.45) 1(19242.5,9447.29) 1(19242.5,9447.29) 1(19242.5,9482.29) 1(19242.5,9482.29) 1(19242.53,11174.91) 1(19242.53,11199.06) 1(19242.53,11237.91) 1(19247.5,9441.45) 1(19247.5,9488.12) 1(19249.37,9837.19) 1(19249.37,9900.19) 1(19252.83,8795.97) 1(19252.83,8795.97) 1(19252.83,8819.3) 1(19252.83,8819.3) 1(19255.33,8790.14) 1(19255.33,8790.14) 1(19255.33,8825.14) 1(19255.33,8825.14) 1(19255.84,11216.91) 1(19258.77,9837.19) 1(19258.77,9900.19) 1(19260.33,8784.3) 1(19260.33,8830.97) 1(19271,9464.79) 1(19271,9464.79) 1(19272,9460.12) 1(19272,9460.12) 1(19272,9469.45) 1(19272,9469.45) 1(19272.29,11237.91) 1(19274,9456.04) 1(19274,9456.04) 1(19274,9473.54) 1(19274,9473.54) 1(19274.28,11070.91) 1(19274.28,11070.91) 1(19274.28,11133.91) 1(19276.99,11174.91) 1(19277,9453.7) 1(19277,9453.7) 1(19277,9475.87) 1(19277,9475.87) 1(19280,9453.12) 1(19280,9453.12) 1(19280,9476.45) 1(19280,9476.45) 1(19283,9453.7) 1(19283,9453.7) 1(19283,9475.87) 1(19283,9475.87) 1(19283.83,8807.64) 1(19283.83,8807.64) 1(19284.83,8802.97) 1(19284.83,8802.97) 1(19284.83,8812.3) 1(19284.83,8812.3) 1(19286,9456.04) 1(19286,9456.04) 1(19286,9473.54) 1(19286,9473.54) 1(19286.83,8798.89) 1(19286.83,8798.89) 1(19286.83,8816.39) 1(19286.83,8816.39) 1(19288,9460.12) 1(19288,9460.12) 1(19288,9469.45) 1(19288,9469.45) 1(19288.5,9464.79) 1(19288.5,9464.79) 1(19289.83,8796.55) 1(19289.83,8796.55) 1(19289.83,8818.72) 1(19289.83,8818.72) 1(19292.83,8795.97) 1(19292.83,8795.97) 1(19292.83,8819.3) 1(19292.83,8819.3) 1(19295.14,9837.19) 1(19295.14,9837.19) 1(19295.14,9900.19) 1(19295.14,9900.19) 1(19295.83,8796.55) 1(19295.83,8796.55) 1(19295.83,8818.72) 1(19295.83,8818.72) 1(19298.83,8798.89) 1(19298.83,8798.89) 1(19298.83,8816.39) 1(19298.83,8816.39) 1(19300.83,8802.97) 1(19300.83,8802.97) 1(19300.83,8812.3) 1(19300.83,8812.3) 1(19301.33,8807.64) 1(19301.33,8807.64) 1(19301.5,9453.12) 1(19301.5,9471.2) 1(19301.5,9488.12) 1(19303.59,11070.91) 1(19303.59,11070.91) 1(19303.59,11103.46) 1(19303.59,11133.91) 1(19303.59,11133.91) 1(19304,9474.12) 1(19304,9474.12) 1(19306.5,9475.87) 1(19306.5,9475.87) 1(19310.5,9476.45) 1(19310.5,9476.45) 1(19310.8,9837.19) 1(19310.8,9837.19) 1(19310.8,9900.19) 1(19310.8,9900.19) 1(19313.36,11174.91) 1(19313.36,11237.91) 1(19313.5,9475.87) 1(19313.5,9475.87) 1(19314.33,8795.97) 1(19314.33,8814.05) 1(19314.33,8830.97) 1(19316.83,8816.97) 1(19316.83,8816.97) 1(19317,9473.54) 1(19317,9473.54) 1(19317.07,9840.34) 1(19317.07,9840.34) 1(19317.07,9897.04) 1(19317.07,9897.04) 1(19318.5,9453.12) 1(19318.5,9470.04) 1(19318.5,9470.04) 1(19319.33,8818.72) 1(19319.33,8818.72) 1(19321.77,9844.54) 1(19321.77,9844.54) 1(19321.77,9892.84) 1(19321.77,9892.84) 1(19322.39,11103.46) 1(19322.76,11174.91) 1(19322.76,11237.91) 1(19323.33,8819.3) 1(19323.33,8819.3) 1(19325,9453.12) 1(19325,9470.04) 1(19325,9476.45) 1(19325.69,9850.84) 1(19325.69,9850.84) 1(19325.69,9886.54) 1(19325.69,9886.54) 1(19326.33,8818.72) 1(19326.33,8818.72) 1(19326.5,9472.95) 1(19326.5,9472.95) 1(19328.82,9858.19) 1(19328.82,9858.19) 1(19328.82,9879.19) 1(19328.82,9879.19) 1(19329,9475.29) 1(19329,9475.29) 1(19329.6,9868.69) 1(19329.6,9868.69) 1(19329.83,8816.39) 1(19329.83,8816.39) 1(19331.33,8795.97) 1(19331.33,8812.89) 1(19331.33,8812.89) 1(19332.16,11174.91) 1(19332.16,11237.91) 1(19332.5,9476.45) 1(19332.5,9476.45) 1(19334.93,11070.91) 1(19334.93,11133.91) 1(19336,9475.29) 1(19336,9475.29) 1(19337.83,8795.97) 1(19337.83,8812.89) 1(19337.83,8819.3) 1(19338.5,9472.95) 1(19338.5,9472.95) 1(19339.33,8815.8) 1(19339.33,8815.8) 1(19340,9453.12) 1(19340,9470.04) 1(19340,9470.04) 1(19340,9470.04) 1(19341.5,9472.95) 1(19341.5,9472.95) 1(19341.83,8818.14) 1(19341.83,8818.14) 1(19344,9475.29) 1(19344,9475.29) 1(19345.33,8819.3) 1(19345.33,8819.3) 1(19347.5,9476.45) 1(19347.5,9476.45) 1(19348.83,8818.14) 1(19348.83,8818.14) 1(19351,9475.29) 1(19351,9475.29) 1(19351.33,8815.8) 1(19351.33,8815.8) 1(19352.83,8795.97) 1(19352.83,8812.89) 1(19352.83,8812.89) 1(19352.83,8812.89) 1(19353.5,9472.95) 1(19353.5,9472.95) 1(19354.33,8815.8) 1(19354.33,8815.8) 1(19355,9453.12) 1(19355,9469.45) 1(19355,9469.45) 1(19356.83,8818.14) 1(19356.83,8818.14) 1(19359.7,9837.19) 1(19359.7,9837.19) 1(19359.7,9869.74) 1(19359.7,9900.19) 1(19359.7,9900.19) 1(19360.33,8819.3) 1(19360.33,8819.3) 1(19363.83,8818.14) 1(19363.83,8818.14) 1(19366.33,8815.8) 1(19366.33,8815.8) 1(19367.74,11174.91) 1(19367.74,11237.91) 1(19367.74,11237.91) 1(19367.83,8795.97) 1(19367.83,8812.3) 1(19367.83,8812.3) 1(19372.5,9441.45) 1(19372.5,9488.12) 1(19377.5,9447.29) 1(19377.5,9447.29) 1(19377.5,9482.29) 1(19377.5,9482.29) 1(19378.5,9869.74) 1(19380,9453.12) 1(19380,9453.12) 1(19380,9476.45) 1(19380,9476.45) 1(19385.33,8784.3) 1(19385.33,8830.97) 1(19390.33,8790.14) 1(19390.33,8790.14) 1(19390.33,8825.14) 1(19390.33,8825.14) 1(19391.04,9837.19) 1(19391.04,9900.19) 1(19392.83,8795.97) 1(19392.83,8795.97) 1(19392.83,8819.3) 1(19392.83,8819.3) 1(19403.78,11174.91) 1(19403.78,11174.91) 1(19403.78,11237.91) 1(19428.39,11203.26) 1(19428.39,11203.26) 1(19428.39,11210.61) 1(19428.39,11210.61) 1(19429.96,11194.86) 1(19429.96,11194.86) 1(19429.96,11216.91) 1(19429.96,11216.91) 1(19433.09,11187.51) 1(19433.09,11187.51) 1(19433.09,11224.26) 1(19433.09,11224.26) 1(19437.79,11181.21) 1(19437.79,11181.21) 1(19437.79,11230.56) 1(19437.79,11230.56) 1(19442.49,11234.76) 1(19442.49,11234.76) 1(19443.28,11177.01) 1(19443.28,11177.01) 1(19448.76,11237.91) 1(19448.76,11237.91) 1(19451.11,11174.91) 1(19451.11,11174.91) 1(19453.46,11206.41) 1(19454.24,11237.91) 1(19454.24,11237.91) 1(19458.94,11177.01) 1(19458.94,11177.01) 1(19460.51,11235.81) 1(19460.51,11235.81) 1(19464.43,11181.21) 1(19464.43,11181.21) 1(19465.21,11231.61) 1(19469.13,11187.51) 1(19469.13,11187.51) 1(19469.13,11206.41) 1(19469.13,11206.41) 1(19469.26,11157.91) 1(19646.12,9443.8) 1(19646.12,9458.38) 1(19646.12,9478.8) 1(19646.12,9478.8) 1(19658.12,9458.38) 1(19658.12,9458.38) 1(19658.12,9478.8) 1(19658.12,9478.8) 1(19662.12,9477.05) 1(19662.12,9477.05) 1(19662.62,9460.13) 1(19662.62,9460.13) 1(19665.12,9463.63) 1(19665.12,9463.63) 1(19665.12,9472.97) 1(19665.12,9472.97) 1(19666.12,9468.3) 1(19666.12,9468.3) 1(19670.94,8796.36) 1(19670.94,8810.94) 1(19670.94,8831.36) 1(19670.94,8831.36) 1(19676.12,9443.8) 1(19676.12,9460.72) 1(19676.12,9478.8) 1(19676.12,9478.8) 1(19682.94,8810.94) 1(19682.94,8810.94) 1(19682.94,8831.36) 1(19682.94,8831.36) 1(19686.94,8829.61) 1(19686.94,8829.61) 1(19687.44,8812.69) 1(19687.44,8812.69) 1(19688.62,9460.72) 1(19688.62,9460.72) 1(19688.62,9460.72) 1(19688.62,9478.8) 1(19688.62,9478.8) 1(19689.94,8816.19) 1(19689.94,8816.19) 1(19689.94,8825.53) 1(19689.94,8825.53) 1(19690.94,8820.86) 1(19690.94,8820.86) 1(19692.12,9462.47) 1(19692.12,9462.47) 1(19692.62,9477.05) 1(19692.62,9477.05) 1(19695.12,9465.38) 1(19695.12,9465.38) 1(19695.12,9474.72) 1(19695.12,9474.72) 1(19696.12,9443.8) 1(19696.12,9470.05) 1(19696.12,9470.05) 1(19700.94,8796.36) 1(19700.94,8813.28) 1(19700.94,8831.36) 1(19700.94,8831.36) 1(19706.12,9443.8) 1(19706.12,9443.8) 1(19706.12,9461.88) 1(19706.12,9478.8) 1(19706.12,9478.8) 1(19713.44,8813.28) 1(19713.44,8813.28) 1(19713.44,8813.28) 1(19713.44,8831.36) 1(19713.44,8831.36) 1(19716.94,8815.03) 1(19716.94,8815.03) 1(19717.44,8829.61) 1(19717.44,8829.61) 1(19718.12,9461.88) 1(19719.94,8817.94) 1(19719.94,8817.94) 1(19719.94,8827.28) 1(19719.94,8827.28) 1(19720.94,8796.36) 1(19720.94,8822.61) 1(19720.94,8822.61) 1(19726.12,9443.8) 1(19726.12,9478.8) 1(19730.94,8796.36) 1(19730.94,8796.36) 1(19730.94,8814.44) 1(19730.94,8831.36) 1(19730.94,8831.36) 1(19733.62,9459.55) 1(19733.62,9459.55) 1(19734.12,9464.8) 1(19734.12,9464.8) 1(19734.62,9454.3) 1(19734.62,9454.3) 1(19736.12,9450.8) 1(19736.12,9450.8) 1(19736.12,9470.63) 1(19736.12,9470.63) 1(19738.62,9474.13) 1(19738.62,9474.13) 1(19739.12,9447.3) 1(19739.12,9447.3) 1(19742.12,9477.05) 1(19742.12,9477.05) 1(19742.62,9444.97) 1(19742.62,9444.97) 1(19742.94,8814.44) 1(19746.12,9443.8) 1(19746.12,9443.8) 1(19746.62,9478.8) 1(19746.62,9478.8) 1(19749.62,9443.8) 1(19749.62,9443.8) 1(19750.62,9478.8) 1(19750.62,9478.8) 1(19750.94,8796.36) 1(19750.94,8831.36) 1(19753.12,9444.97) 1(19753.12,9444.97) 1(19754.12,9477.63) 1(19754.12,9477.63) 1(19756.12,9446.72) 1(19756.12,9446.72) 1(19757.12,9475.88) 1(19758.44,8812.11) 1(19758.44,8812.11) 1(19758.62,9449.05) 1(19758.94,8817.36) 1(19758.94,8817.36) 1(19759.44,8806.86) 1(19759.44,8806.86) 1(19760.94,8803.36) 1(19760.94,8803.36) 1(19760.94,8823.19) 1(19760.94,8823.19) 1(19763.44,8826.69) 1(19763.44,8826.69) 1(19763.94,8799.86) 1(19763.94,8799.86) 1(19766.94,8829.61) 1(19766.94,8829.61) 1(19767.44,8797.53) 1(19767.44,8797.53) 1(19770.12,9443.8) 1(19770.12,9478.8) 1(19770.94,8796.36) 1(19770.94,8796.36) 1(19771.44,8831.36) 1(19771.44,8831.36) 1(19774.44,8796.36) 1(19774.44,8796.36) 1(19775.44,8831.36) 1(19775.44,8831.36) 1(19776.12,9443.8) 1(19776.12,9478.8) 1(19777.94,8797.53) 1(19777.94,8797.53) 1(19778.94,8830.19) 1(19778.94,8830.19) 1(19780.94,8799.28) 1(19780.94,8799.28) 1(19781.94,8828.44) 1(19782.12,9443.8) 1(19782.12,9478.8) 1(19783.44,8801.61) 1(19794.94,8796.36) 1(19794.94,8831.36) 1(19795.62,9448.47) 1(19797.62,9470.05) 1(19797.62,9470.05) 1(19798.62,9474.13) 1(19798.62,9474.13) 1(19799.12,9465.97) 1(19799.12,9465.97) 1(19799.62,9445.55) 1(19799.62,9445.55) 1(19800.94,8796.36) 1(19800.94,8831.36) 1(19801.12,9477.05) 1(19801.12,9477.05) 1(19802.62,9463.63) 1(19802.62,9463.63) 1(19804.12,9443.8) 1(19804.12,9443.8) 1(19804.62,9478.8) 1(19804.62,9478.8) 1(19806.94,8796.36) 1(19806.94,8831.36) 1(19808.12,9443.8) 1(19808.12,9443.8) 1(19808.12,9478.8) 1(19808.12,9478.8) 1(19808.62,9462.47) 1(19808.62,9462.47) 1(19811.62,9477.63) 1(19811.62,9477.63) 1(19812.12,9445.55) 1(19812.12,9445.55) 1(19813.12,9460.13) 1(19813.12,9460.13) 1(19814.62,9474.72) 1(19815.12,9448.47) 1(19815.12,9448.47) 1(19815.62,9456.63) 1(19815.62,9456.63) 1(19816.62,9452.55) 1(19816.62,9452.55) 1(19820.44,8801.03) 1(19822.44,8822.61) 1(19822.44,8822.61) 1(19823.44,8826.69) 1(19823.44,8826.69) 1(19823.94,8818.53) 1(19823.94,8818.53) 1(19824.44,8798.11) 1(19824.44,8798.11) 1(19825.94,8829.61) 1(19825.94,8829.61) 1(19827.44,8816.19) 1(19827.44,8816.19) 1(19828.94,8796.36) 1(19828.94,8796.36) 1(19829.44,8831.36) 1(19829.44,8831.36) 1(19830.12,9443.8) 1(19830.12,9478.8) 1(19832.94,8796.36) 1(19832.94,8796.36) 1(19832.94,8831.36) 1(19832.94,8831.36) 1(19833.44,8815.03) 1(19833.44,8815.03) 1(19836.12,9443.8) 1(19836.12,9478.8) 1(19836.44,8830.19) 1(19836.44,8830.19) 1(19836.94,8798.11) 1(19836.94,8798.11) 1(19837.94,8812.69) 1(19837.94,8812.69) 1(19839.44,8827.28) 1(19839.94,8801.03) 1(19839.94,8801.03) 1(19840.44,8809.19) 1(19840.44,8809.19) 1(19841.44,8805.11) 1(19841.44,8805.11) 1(19842.12,9443.8) 1(19842.12,9478.8) 1(19852.62,9458.97) 1(19852.62,9458.97) 1(19852.62,9463.63) 1(19852.62,9463.63) 1(19853.62,9454.3) 1(19853.62,9454.3) 1(19853.62,9468.3) 1(19853.62,9468.3) 1(19854.94,8796.36) 1(19854.94,8831.36) 1(19855.62,9450.22) 1(19855.62,9450.22) 1(19855.62,9472.38) 1(19855.62,9472.38) 1(19857.56,10160.39) 1(19857.56,10380.07) 1(19857.56,10599.76) 1(19858.62,9446.72) 1(19858.62,9446.72) 1(19858.62,9475.88) 1(19858.62,9475.88) 1(19860.94,8796.36) 1(19860.94,8831.36) 1(19862.12,9444.38) 1(19862.12,9444.38) 1(19862.12,9478.22) 1(19862.12,9478.22) 1(19866.12,9443.8) 1(19866.12,9443.8) 1(19866.12,9478.8) 1(19866.12,9478.8) 1(19866.94,8796.36) 1(19866.94,8831.36) 1(19870.12,9444.38) 1(19870.12,9444.38) 1(19870.12,9478.22) 1(19870.12,9478.22) 1(19873.62,9446.72) 1(19873.62,9446.72) 1(19873.62,9475.88) 1(19873.62,9475.88) 1(19876.62,9450.22) 1(19876.62,9450.22) 1(19876.62,9472.38) 1(19876.62,9472.38) 1(19877.44,8811.53) 1(19877.44,8811.53) 1(19877.44,8816.19) 1(19877.44,8816.19) 1(19878.44,8806.86) 1(19878.44,8806.86) 1(19878.44,8820.86) 1(19878.44,8820.86) 1(19878.62,9454.3) 1(19878.62,9454.3) 1(19878.62,9468.3) 1(19878.62,9468.3) 1(19879.62,9458.97) 1(19879.62,9458.97) 1(19879.62,9463.63) 1(19879.62,9463.63) 1(19880.44,8802.78) 1(19880.44,8802.78) 1(19880.44,8824.94) 1(19880.44,8824.94) 1(19883.44,8799.28) 1(19883.44,8799.28) 1(19883.44,8828.44) 1(19883.44,8828.44) 1(19884.62,9443.8) 1(19884.62,9478.8) 1(19884.62,9478.8) 1(19886.94,8796.94) 1(19886.94,8796.94) 1(19886.94,8830.78) 1(19886.94,8830.78) 1(19890.94,8796.36) 1(19890.94,8796.36) 1(19890.94,8831.36) 1(19890.94,8831.36) 1(19894.94,8796.94) 1(19894.94,8796.94) 1(19894.94,8830.78) 1(19894.94,8830.78) 1(19898.44,8799.28) 1(19898.44,8799.28) 1(19898.44,8828.44) 1(19898.44,8828.44) 1(19901.44,8802.78) 1(19901.44,8802.78) 1(19901.44,8824.94) 1(19901.44,8824.94) 1(19903.44,8806.86) 1(19903.44,8806.86) 1(19903.44,8820.86) 1(19903.44,8820.86) 1(19904.44,8811.53) 1(19904.44,8811.53) 1(19904.44,8816.19) 1(19904.44,8816.19) 1(19907.56,10160.39) 1(19907.56,10380.07) 1(19907.56,10599.76) 1(19907.62,9443.8) 1(19907.62,9443.8) 1(19907.62,9478.8) 1(19909.44,8796.36) 1(19909.44,8831.36) 1(19909.44,8831.36) 1(19932.44,8796.36) 1(19932.44,8796.36) 1(19932.44,8831.36) 1(19957.56,10160.39) 1(19957.56,10380.07) 1(19957.56,10599.76) 1(19967.56,10050.39) 1(19967.56,10270.07) 1(19967.56,10489.76) 1(20007.56,10160.39) 1(20007.56,10380.07) 1(20007.56,10599.76) 1(20017.56,10050.39) 1(20017.56,10270.07) 1(20017.56,10489.76) 1(20057.56,10160.39) 1(20057.56,10380.07) 1(20057.56,10599.76) 1(20067.56,10050.39) 1(20067.56,10270.07) 1(20067.56,10489.76) 1(20117.56,10050.39) 1(20117.56,10100.39) 1(20117.56,10270.07) 1(20117.56,10320.07) 1(20117.56,10489.76) 1(20117.56,10539.76) 1(20135.45,9995.03) 1(20135.45,9995.03) 1(20135.45,9995.03) 1(20135.45,10215.03) 1(20135.45,10215.03) 1(20135.45,10215.03) 1(20135.45,10435.03) 1(20135.45,10435.03) 1(20135.45,10435.03) 1(20135.45,10655.03) 1(20135.45,10655.03) 1(20135.45,10655.03) 1(20190.45,9975.03) 1(20190.45,9975.03) 1(20190.45,10015.03) 1(20190.45,10015.03) 1(20190.45,10195.03) 1(20190.45,10195.03) 1(20190.45,10235.03) 1(20190.45,10235.03) 1(20190.45,10415.03) 1(20190.45,10415.03) 1(20190.45,10455.03) 1(20190.45,10455.03) 1(20190.45,10635.03) 1(20190.45,10635.03) 1(20190.45,10675.03) 1(20190.45,10675.03) 1(20271.45,9995.03) 1(20271.45,10215.03) 1(20271.45,10435.03) 1(20271.45,10655.03) 1(20344.03,9969.76) 1(20344.03,9969.76) 1(20344.03,10011.76) 1(20344.03,10011.76) 1(20344.03,10189.76) 1(20344.03,10189.76) 1(20344.03,10231.76) 1(20344.03,10231.76) 1(20344.03,10409.76) 1(20344.03,10409.76) 1(20344.03,10451.76) 1(20344.03,10451.76) 1(20344.03,10629.76) 1(20344.03,10629.76) 1(20344.03,10671.76) 1(20344.03,10671.76) 1(20347.95,9959.26) 1(20347.95,9959.26) 1(20347.95,10022.26) 1(20347.95,10022.26) 1(20347.95,10179.26) 1(20347.95,10179.26) 1(20347.95,10242.26) 1(20347.95,10242.26) 1(20347.95,10399.26) 1(20347.95,10399.26) 1(20347.95,10462.26) 1(20347.95,10462.26) 1(20347.95,10619.26) 1(20347.95,10619.26) 1(20347.95,10682.26) 1(20347.95,10682.26) 1(20355.78,9948.76) 1(20355.78,10032.76) 1(20355.78,10168.76) 1(20355.78,10252.76) 1(20355.78,10388.76) 1(20355.78,10472.76) 1(20355.78,10608.76) 1(20355.78,10692.76) 1(20867.62,9948.76) 1(20867.62,10032.76) 1(20867.62,10168.76) 1(20867.62,10252.76) 1(20867.62,10388.76) 1(20867.62,10472.76) 1(20875.45,9959.26) 1(20875.45,9959.26) 1(20875.45,10022.26) 1(20875.45,10022.26) 1(20875.45,10179.26) 1(20875.45,10179.26) 1(20875.45,10242.26) 1(20875.45,10242.26) 1(20875.45,10399.26) 1(20875.45,10399.26) 1(20875.45,10462.26) 1(20875.45,10462.26) 1(20878.41,10608.85) 1(20878.41,10692.85) 1(20879.37,9969.76) 1(20879.37,9969.76) 1(20879.37,10011.76) 1(20879.37,10011.76) 1(20879.37,10189.76) 1(20879.37,10189.76) 1(20879.37,10231.76) 1(20879.37,10231.76) 1(20879.37,10409.76) 1(20879.37,10409.76) 1(20879.37,10451.76) 1(20879.37,10451.76) 1(20886.24,10619.35) 1(20886.24,10619.35) 1(20886.24,10682.35) 1(20886.24,10682.35) 1(20890.16,10629.85) 1(20890.16,10629.85) 1(20890.16,10671.85) 1(20890.16,10671.85) 1(20928.59,9448.81) 1(20928.59,9465.73) 1(20928.59,9483.81) 1(20928.59,9483.81) 1(20941.02,8808.18) 1(20941.02,8825.1) 1(20941.02,8843.18) 1(20941.02,8843.18) 1(20941.09,9465.73) 1(20941.09,9465.73) 1(20941.09,9465.73) 1(20941.09,9483.81) 1(20941.09,9483.81) 1(20944.59,9467.48) 1(20944.59,9467.48) 1(20945.09,9482.06) 1(20945.09,9482.06) 1(20947.59,9470.39) 1(20947.59,9470.39) 1(20947.59,9479.73) 1(20947.59,9479.73) 1(20948.59,9448.81) 1(20948.59,9475.06) 1(20948.59,9475.06) 1(20953.52,8825.1) 1(20953.52,8825.1) 1(20953.52,8825.1) 1(20953.52,8843.18) 1(20953.52,8843.18) 1(20957.02,8826.85) 1(20957.02,8826.85) 1(20957.52,8841.43) 1(20957.52,8841.43) 1(20958.59,9448.81) 1(20958.59,9448.81) 1(20958.59,9466.89) 1(20958.59,9483.81) 1(20958.59,9483.81) 1(20960.02,8829.76) 1(20960.02,8829.76) 1(20960.02,8839.1) 1(20960.02,8839.1) 1(20961.02,8808.18) 1(20961.02,8834.43) 1(20961.02,8834.43) 1(20970.59,9466.89) 1(20971.02,8808.18) 1(20971.02,8808.18) 1(20971.02,8826.26) 1(20971.02,8843.18) 1(20971.02,8843.18) 1(20978.59,9448.81) 1(20978.59,9483.81) 1(20983.02,8826.26) 1(20985.59,9448.81) 1(20985.59,9483.81) 1(20985.59,9483.81) 1(20991.02,8808.18) 1(20991.02,8843.18) 1(20998.02,8808.18) 1(20998.02,8843.18) 1(20998.02,8843.18) 1(20998.59,9454.64) 1(20998.59,9454.64) 1(21011.02,8814.01) 1(21011.02,8814.01) 1(21011.59,9448.81) 1(21011.59,9483.81) 1(21011.59,9483.81) 1(21016.09,9448.81) 1(21020.59,9461.06) 1(21024.02,8808.18) 1(21024.02,8843.18) 1(21024.02,8843.18) 1(21028.52,8808.18) 1(21028.59,9483.81) 1(21028.59,9483.81) 1(21033.02,8820.43) 1(21036.59,9461.06) 1(21041.02,8843.18) 1(21041.02,8843.18) 1(21041.09,9448.81) 1(21048.59,9448.81) 1(21048.59,9465.73) 1(21048.59,9483.81) 1(21048.59,9483.81) 1(21049.02,8820.43) 1(21053.52,8808.18) 1(21061.02,8808.18) 1(21061.02,8825.1) 1(21061.02,8843.18) 1(21061.02,8843.18) 1(21061.09,9465.73) 1(21061.09,9465.73) 1(21061.09,9465.73) 1(21061.09,9483.81) 1(21061.09,9483.81) 1(21064.59,9467.48) 1(21064.59,9467.48) 1(21065.09,9482.06) 1(21065.09,9482.06) 1(21067.59,9470.39) 1(21067.59,9470.39) 1(21067.59,9479.73) 1(21067.59,9479.73) 1(21068.59,9448.81) 1(21068.59,9475.06) 1(21068.59,9475.06) 1(21073.52,8825.1) 1(21073.52,8825.1) 1(21073.52,8825.1) 1(21073.52,8843.18) 1(21073.52,8843.18) 1(21077.02,8826.85) 1(21077.02,8826.85) 1(21077.52,8841.43) 1(21077.52,8841.43) 1(21077.59,9448.81) 1(21077.59,9462.23) 1(21077.59,9483.81) 1(21080.02,8829.76) 1(21080.02,8829.76) 1(21080.02,8839.1) 1(21080.02,8839.1) 1(21081.02,8808.18) 1(21081.02,8834.43) 1(21081.02,8834.43) 1(21086.09,9472.14) 1(21090.02,8808.18) 1(21090.02,8821.6) 1(21090.02,8843.18) 1(21096.59,9483.81) 1(21098.52,8831.51) 1(21099.59,9448.81) 1(21109.02,8843.18) 1(21112.02,8808.18)
  round 10 on Drill Drawing: 1(18031.55,9941.13) 1(18031.55,9941.13) 1(18031.55,9941.13) 1(18031.55,10050.97) 1(18031.55,10160.81) 1(18031.55,10270.66) 1(18031.55,10380.5) 1(18031.55,10490.34) 1(18031.55,10600.18) 1(18031.55,10710.03) 1(18031.55,10710.03) 1(20118.56,9941.13) 1(20118.56,9941.13) 1(20118.56,9941.13) 1(20118.56,10050.97) 1(20118.56,10160.81) 1(20118.56,10270.66) 1(20118.56,10380.5) 1(20118.56,10490.34) 1(20118.56,10600.18) 1(20118.56,10710.03) 1(20118.56,10710.03)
